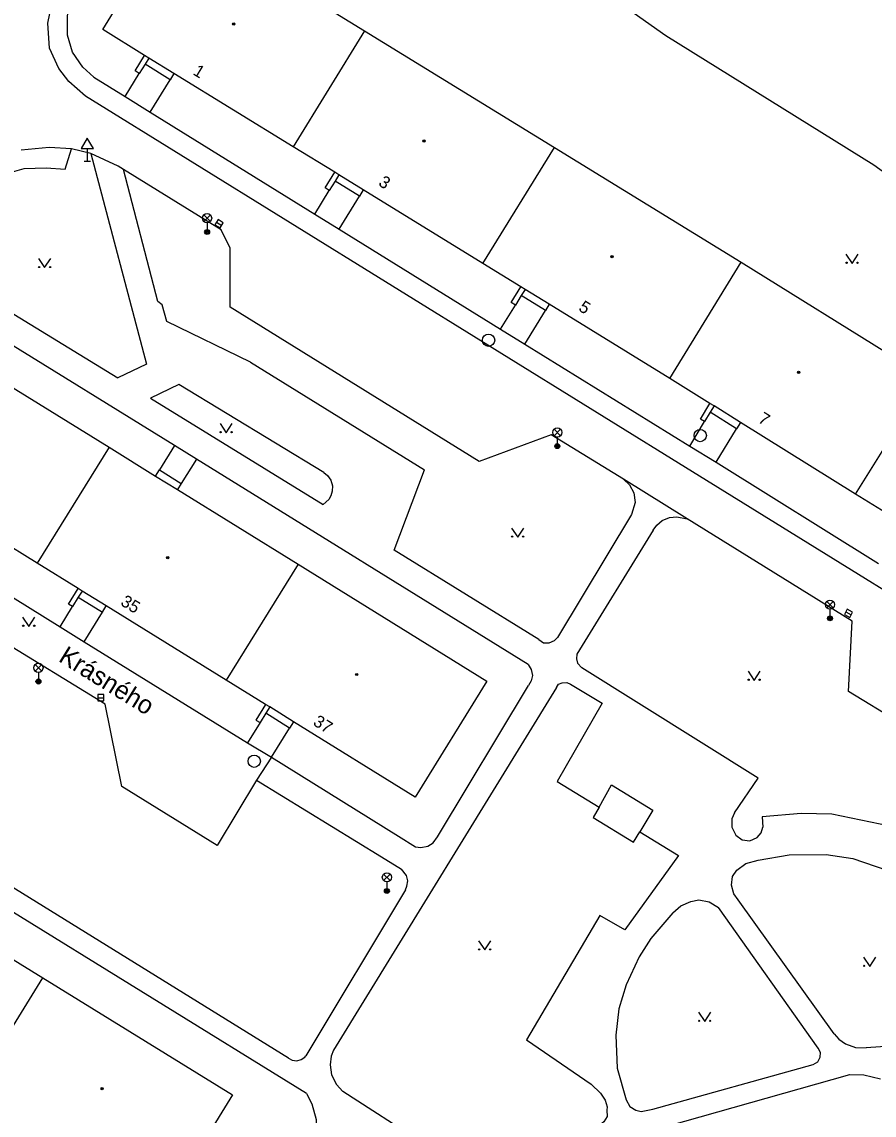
# Model space of a CAD drawing. Extents: x -598341 to -594502, y -1162301 to -1161406.
# Drawn here: x -594775.2 to -594705.4, y -1161589.1 to -1161499.6 of the extents above; entities that cross this region are included whole.
import ezdxf

# ---------------------------------------------------------------- set-up
doc = ezdxf.new("R2010")
doc.units = 0
for name, color, linetype in [('Vrstva 10', 7, 'Continuous'), ('Vrstva 11', 7, 'Continuous'), ('Vrstva 27', 7, 'Continuous'), ('Vrstva 33', 7, 'Continuous'), ('Vrstva 34', 7, 'Continuous'), ('Vrstva 36', 7, 'Continuous'), ('Vrstva 39', 7, 'Continuous'), ('Vrstva 46', 7, 'Continuous'), ('Vrstva 49', 7, 'Continuous'), ('Vrstva 5', 7, 'Continuous')]:
    doc.layers.add(name, color=color, linetype=linetype)

msp = doc.modelspace()

# ---------------------------------------------------------------- linework, layer by layer
at = {"layer": 'Vrstva 10'}
for p, q in [((-594772.93, -1161509.91), (-594775.22, -1161510.13)), ((-594771.1, -1161510.03), (-594772.93, -1161509.91)), ((-594769.52, -1161510.41), (-594771.1, -1161510.03)), ((-594767.27, -1161511.46), (-594769.52, -1161510.41)), ((-594766.83, -1161511.73), (-594767.27, -1161511.46)), ((-594758.85, -1161516.66), (-594766.83, -1161511.73)), ((-594758.11, -1161518.16), (-594758.85, -1161516.66)), ((-594758.12, -1161522.99), (-594758.11, -1161518.16)), ((-594737.73, -1161535.61), (-594758.12, -1161522.99)), ((-594731.85, -1161533.43), (-594737.73, -1161535.61)), ((-594725.93, -1161537.07), (-594731.85, -1161533.43)), ((-594720.72, -1161540.31), (-594725.93, -1161537.07)), ((-594785.33, -1161540.9), (-594772.03, -1161549.14)), ((-594707.22, -1161548.68), (-594720.72, -1161540.31)), ((-594768.35, -1161555.47), (-594789.84, -1161542.3)), ((-594707.53, -1161554.42), (-594707.22, -1161548.68)), ((-594772.03, -1161549.14), (-594770.06, -1161550.36)), ((-594770.06, -1161550.36), (-594756.69, -1161558.63)), ((-594697.74, -1161560.45), (-594707.53, -1161554.42)), ((-594766.98, -1161562.21), (-594768.35, -1161555.47)), ((-594756.69, -1161558.63), (-594754.73, -1161559.81)), ((-594754.73, -1161559.81), (-594755.95, -1161561.69)), ((-594759.18, -1161567.03), (-594766.98, -1161562.21)), ((-594755.95, -1161561.69), (-594759.18, -1161567.03))]:
    msp.add_line(p, q, dxfattribs=at)
for points in [[(-594771.32, -1161504.52), (-594772.13, -1161503.46), (-594772.9, -1161501.78), (-594773.04, -1161499.76), (-594772.69, -1161498.16), (-594772.22, -1161497.2)], [(-594615.8, -1161601.07), (-594662.39, -1161572.26), (-594719.72, -1161536.81), (-594769.96, -1161505.71), (-594771.32, -1161504.52)]]:
    msp.add_lwpolyline(points, dxfattribs=at)
at = {"layer": 'Vrstva 11'}
for p, q in [((-594765.08, -1161503.11), (-594765.55, -1161503.87)), ((-594764.76, -1161502.6), (-594765.08, -1161503.11)), ((-594763.02, -1161504.37), (-594765.08, -1161503.11)), ((-594769.26, -1161504.17), (-594766.7, -1161505.74)), ((-594766.7, -1161505.74), (-594765.55, -1161503.87)), ((-594762.71, -1161503.86), (-594763.02, -1161504.37)), ((-594764.65, -1161507.02), (-594763.02, -1161504.37)), ((-594766.7, -1161505.74), (-594764.65, -1161507.02)), ((-594764.65, -1161507.02), (-594751.18, -1161515.37)), ((-594771.62, -1161511.7), (-594771.1, -1161510.03)), ((-594749.21, -1161512.16), (-594749.52, -1161512.68)), ((-594749.52, -1161512.68), (-594750, -1161513.44)), ((-594747.54, -1161513.9), (-594749.52, -1161512.68)), ((-594751.18, -1161515.37), (-594750, -1161513.44)), ((-594749.2, -1161516.59), (-594747.54, -1161513.9)), ((-594747.23, -1161513.38), (-594747.54, -1161513.9)), ((-594751.18, -1161515.37), (-594749.2, -1161516.59)), ((-594749.2, -1161516.59), (-594735.99, -1161524.79)), ((-594781.79, -1161519.92), (-594767.3, -1161528.78)), ((-594762.67, -1161534.31), (-594783.13, -1161521.66)), ((-594734.3, -1161522.04), (-594734.77, -1161522.81)), ((-594733.98, -1161521.53), (-594734.3, -1161522.04)), ((-594732.32, -1161523.26), (-594734.3, -1161522.04)), ((-594735.99, -1161524.79), (-594734.77, -1161522.81)), ((-594732, -1161522.75), (-594732.32, -1161523.26)), ((-594734.01, -1161526.01), (-594732.32, -1161523.26)), ((-594735.99, -1161524.79), (-594734.01, -1161526.01)), ((-594734.01, -1161526.01), (-594720.51, -1161534.35)), ((-594756.45, -1161527.48), (-594742.22, -1161536.29)), ((-594750.46, -1161536.5), (-594762.3, -1161529.31)), ((-594718.52, -1161531.07), (-594718.84, -1161531.58)), ((-594718.84, -1161531.58), (-594719.3, -1161532.35)), ((-594716.68, -1161532.93), (-594718.84, -1161531.58)), ((-594720.51, -1161534.35), (-594719.3, -1161532.35)), ((-594716.36, -1161532.41), (-594716.68, -1161532.93)), ((-594718.34, -1161535.68), (-594716.68, -1161532.93)), ((-594762.67, -1161534.31), (-594763.9, -1161536.3)), ((-594760.88, -1161535.42), (-594762.67, -1161534.31)), ((-594720.51, -1161534.35), (-594718.34, -1161535.68)), ((-594760.88, -1161535.42), (-594762.11, -1161537.4)), ((-594733.72, -1161552.21), (-594760.88, -1161535.42)), ((-594764.21, -1161536.81), (-594763.9, -1161536.3)), ((-594763.9, -1161536.3), (-594762.11, -1161537.4)), ((-594718.34, -1161535.68), (-594705.07, -1161543.95)), ((-594762.11, -1161537.4), (-594762.42, -1161537.91)), ((-594725.28, -1161539.94), (-594731.34, -1161550.01)), ((-594723.5, -1161541.22), (-594729.74, -1161551.37)), ((-594770.22, -1161546.21), (-594770.54, -1161546.72)), ((-594770.54, -1161546.72), (-594771.01, -1161547.49)), ((-594770.54, -1161546.72), (-594768.56, -1161547.94)), ((-594772.03, -1161549.14), (-594771.01, -1161547.49)), ((-594770.06, -1161550.36), (-594768.56, -1161547.94)), ((-594768.56, -1161547.94), (-594768.25, -1161547.43)), ((-594731.42, -1161554.11), (-594749.67, -1161583.78)), ((-594741.15, -1161566.33), (-594733.71, -1161553.95)), ((-594754.88, -1161555.7), (-594755.2, -1161556.21)), ((-594755.67, -1161556.98), (-594756.69, -1161558.63)), ((-594755.2, -1161556.21), (-594755.67, -1161556.98)), ((-594753.25, -1161557.42), (-594755.2, -1161556.21)), ((-594752.93, -1161556.91), (-594753.25, -1161557.42)), ((-594754.73, -1161559.81), (-594753.25, -1161557.42)), ((-594755.95, -1161561.69), (-594745.72, -1161567.97)), ((-594712.38, -1161567.8), (-594709.36, -1161567.77)), ((-594745.72, -1161567.97), (-594744.1, -1161568.97)), ((-594751.86, -1161587.33), (-594781.69, -1161568.93)), ((-594743.76, -1161570.67), (-594751.92, -1161584.24)), ((-594710.01, -1161583.61), (-594718.16, -1161572.11)), ((-594708.69, -1161582.44), (-594716.56, -1161571.48)), ((-594721.9, -1161572.55), (-594723.7, -1161574.64)), ((-594722.37, -1161590.01), (-594707.41, -1161585.76))]:
    msp.add_line(p, q, dxfattribs=at)
for points in [[(-594744.77, -1161484.99), (-594722.47, -1161500.75), (-594705.44, -1161511.34), (-594693.39, -1161520.03), (-594678.98, -1161528.27), (-594666.01, -1161534.88), (-594661.61, -1161528.62)], [(-594769.26, -1161504.17), (-594770.18, -1161503.36), (-594771.01, -1161502.13), (-594771.43, -1161500.74), (-594771.43, -1161499.13), (-594771.1, -1161497.8)], [(-594765.55, -1161503.87), (-594765.89, -1161503.66), (-594765.11, -1161502.38)], [(-594769.52, -1161510.41), (-594764.96, -1161527.66), (-594767.3, -1161528.78)], [(-594780, -1161513.97), (-594778.7, -1161513.04), (-594776.88, -1161512.17), (-594774.96, -1161511.65), (-594773.18, -1161511.58), (-594771.62, -1161511.7)], [(-594756.45, -1161527.48), (-594763.3, -1161524.17), (-594763.67, -1161522.79), (-594764.02, -1161522.53), (-594766.83, -1161511.73)], [(-594750, -1161513.44), (-594750.34, -1161513.23), (-594749.55, -1161511.95)], [(-594734.77, -1161522.81), (-594735.11, -1161522.6), (-594734.32, -1161521.32)], [(-594762.3, -1161529.31), (-594764.64, -1161530.42), (-594750.5, -1161539.14)], [(-594719.3, -1161532.35), (-594719.64, -1161532.14), (-594718.86, -1161530.86)], [(-594732.86, -1161550.19), (-594744.7, -1161542.87), (-594742.22, -1161536.29)], [(-594750.46, -1161536.5), (-594750.14, -1161536.77), (-594749.89, -1161537.13), (-594749.75, -1161537.6), (-594749.76, -1161538.04), (-594749.88, -1161538.42), (-594750.03, -1161538.71), (-594750.5, -1161539.14)], [(-594725.93, -1161537.07), (-594725.44, -1161537.51), (-594725.08, -1161538.18), (-594724.99, -1161538.96), (-594725.28, -1161539.94)], [(-594723.5, -1161541.22), (-594723.21, -1161540.81), (-594722.77, -1161540.45), (-594722.18, -1161540.2), (-594721.57, -1161540.13), (-594720.72, -1161540.31)], [(-594771.01, -1161547.49), (-594771.35, -1161547.28), (-594770.56, -1161546)], [(-594732.86, -1161550.19), (-594732.47, -1161550.44), (-594732, -1161550.46), (-594731.58, -1161550.25), (-594731.34, -1161550.01)], [(-594729.74, -1161551.37), (-594729.78, -1161551.77), (-594729.69, -1161552.1), (-594729.33, -1161552.5)], [(-594733.72, -1161552.21), (-594733.48, -1161552.64), (-594733.39, -1161553.13), (-594733.48, -1161553.55), (-594733.71, -1161553.95)], [(-594716.84, -1161564.36), (-594714.9, -1161561.53), (-594729.33, -1161552.5)], [(-594753.34, -1161584.44), (-594799.98, -1161555.58), (-594802.68, -1161553.27)], [(-594731.42, -1161554.11), (-594731.25, -1161553.84), (-594730.95, -1161553.71), (-594730.56, -1161553.69), (-594730.28, -1161553.82)], [(-594730.28, -1161553.82), (-594727.67, -1161555.39), (-594731.36, -1161561.79), (-594727.92, -1161563.89)], [(-594755.22, -1161555.49), (-594756.01, -1161556.77), (-594755.67, -1161556.98)], [(-594754.73, -1161559.81), (-594744.34, -1161566.28), (-594742.96, -1161567.14)], [(-594727.92, -1161563.89), (-594726.91, -1161562.07), (-594723.52, -1161564.14), (-594724.6, -1161565.92)], [(-594727.92, -1161563.89), (-594728.4, -1161564.74), (-594725.11, -1161566.75), (-594724.6, -1161565.92)], [(-594716.84, -1161564.36), (-594717.06, -1161564.85), (-594717.08, -1161565.53), (-594716.75, -1161566.19), (-594716.23, -1161566.58), (-594715.6, -1161566.65), (-594714.99, -1161566.38), (-594714.66, -1161566), (-594714.53, -1161565.54)], [(-594704.2, -1161566.94), (-594704.14, -1161565.46), (-594708.88, -1161564.48), (-594711.39, -1161564.42), (-594714.58, -1161564.68), (-594714.53, -1161565.54)], [(-594724.6, -1161565.92), (-594721.44, -1161567.84), (-594725.83, -1161573.92), (-594727.86, -1161572.75), (-594733.86, -1161582.92), (-594728.58, -1161586.55), (-594727.81, -1161587.31)], [(-594742.96, -1161567.14), (-594742.5, -1161567.2), (-594741.93, -1161567.08), (-594741.51, -1161566.81), (-594741.15, -1161566.33)], [(-594716.56, -1161571.48), (-594716.9, -1161570.98), (-594717.1, -1161570.29), (-594717.01, -1161569.58), (-594716.66, -1161569.06), (-594715.93, -1161568.5), (-594714.91, -1161568.22), (-594712.38, -1161567.8)], [(-594709.36, -1161567.77), (-594707.17, -1161568.1), (-594704.38, -1161569.05), (-594702.46, -1161570.09), (-594700.74, -1161571.46)], [(-594743.76, -1161570.67), (-594743.66, -1161570.37), (-594743.59, -1161569.92), (-594743.69, -1161569.5), (-594744.1, -1161568.97)], [(-594721.9, -1161572.55), (-594721.25, -1161571.97), (-594720.43, -1161571.62), (-594719.77, -1161571.48), (-594718.91, -1161571.64), (-594718.16, -1161572.11)], [(-594723.7, -1161574.64), (-594724.66, -1161576.13), (-594725.71, -1161578.44), (-594726.3, -1161580.39), (-594726.55, -1161582.56), (-594726.44, -1161585.25), (-594725.71, -1161587.83), (-594725.4, -1161588.38), (-594724.92, -1161588.69), (-594724.48, -1161588.8)], [(-594708.69, -1161582.44), (-594708.3, -1161582.87), (-594707.77, -1161583.25), (-594706.95, -1161583.55), (-594706.08, -1161583.58)], [(-594699.75, -1161582.82), (-594703.35, -1161583.4), (-594706.08, -1161583.58)], [(-594749.67, -1161583.78), (-594749.85, -1161584.27), (-594749.92, -1161584.97), (-594749.82, -1161585.8), (-594749.42, -1161586.59), (-594748.89, -1161587.16)], [(-594710.42, -1161584.96), (-594710.04, -1161584.73), (-594709.83, -1161584.35), (-594709.82, -1161583.97), (-594710.01, -1161583.61)], [(-594753.34, -1161584.44), (-594753.03, -1161584.6), (-594752.66, -1161584.65), (-594752.3, -1161584.55), (-594752, -1161584.36), (-594751.92, -1161584.24)], [(-594724.48, -1161588.8), (-594723.52, -1161588.62), (-594710.42, -1161584.96)], [(-594707.41, -1161585.76), (-594706.26, -1161585.8), (-594704.9, -1161586.12)], [(-594751.86, -1161587.33), (-594751.44, -1161588.17), (-594751.09, -1161589.44), (-594751.07, -1161589.92), (-594751.01, -1161590.71), (-594751.18, -1161591.7), (-594751.76, -1161592.82)], [(-594740.61, -1161592.43), (-594742.38, -1161591.35), (-594748.89, -1161587.16)], [(-594727.81, -1161587.31), (-594727.43, -1161587.87), (-594727.28, -1161588.41), (-594727.29, -1161588.7), (-594727.28, -1161589.2), (-594727.54, -1161589.65), (-594727.95, -1161589.97)]]:
    msp.add_lwpolyline(points, dxfattribs=at)
at = {"layer": 'Vrstva 27'}
for p, q in [((-594759.232, -1161516.027), (-594758.808, -1161516.293)), ((-594707.741, -1161547.923), (-594707.299, -1161548.157)), ((-594768.94, -1161554.94), (-594768.44, -1161554.94))]:
    msp.add_line(p, q, dxfattribs=at)
for points in [[(-594759.365, -1161516.239), (-594758.941, -1161516.505), (-594758.675, -1161516.081), (-594759.099, -1161515.815)], [(-594707.858, -1161548.144), (-594707.416, -1161548.378), (-594707.182, -1161547.936), (-594707.624, -1161547.702)], [(-594768.94, -1161555.19), (-594768.44, -1161555.19), (-594768.44, -1161554.69), (-594768.94, -1161554.69)]]:
    msp.add_lwpolyline(points, close=True, dxfattribs=at)
for centre in [(-594736.97, -1161525.69), (-594719.65, -1161533.49), (-594756.14, -1161560.14)]:
    msp.add_circle(centre, 0.5, dxfattribs=at)
at = {"layer": 'Vrstva 33'}
for p, q in [((-594760.265, -1161515.97), (-594759.735, -1161515.44)), ((-594760.265, -1161515.44), (-594759.735, -1161515.97)), ((-594760, -1161516.08), (-594760, -1161516.83)), ((-594731.615, -1161533.5), (-594731.085, -1161532.97)), ((-594731.615, -1161532.97), (-594731.085, -1161533.5)), ((-594731.35, -1161533.61), (-594731.35, -1161534.36)), ((-594709.305, -1161547.59), (-594708.775, -1161547.06)), ((-594709.305, -1161547.06), (-594708.775, -1161547.59)), ((-594709.04, -1161547.7), (-594709.04, -1161548.45)), ((-594774.065, -1161552.76), (-594773.535, -1161552.23)), ((-594774.065, -1161552.23), (-594773.535, -1161552.76)), ((-594773.8, -1161552.87), (-594773.8, -1161553.62)), ((-594745.555, -1161569.9), (-594745.025, -1161569.37)), ((-594745.555, -1161569.37), (-594745.025, -1161569.9)), ((-594745.29, -1161570.01), (-594745.29, -1161570.76))]:
    msp.add_line(p, q, dxfattribs=at)
for centre, radius in [((-594760, -1161515.705), 0.375), ((-594760, -1161516.83), 0.2), ((-594760, -1161516.83), 0.145), ((-594760, -1161516.83), 0.0876), ((-594731.35, -1161533.235), 0.375), ((-594731.35, -1161534.36), 0.2), ((-594731.35, -1161534.36), 0.145), ((-594731.35, -1161534.36), 0.0876), ((-594709.04, -1161547.325), 0.375), ((-594709.04, -1161548.45), 0.2), ((-594709.04, -1161548.45), 0.145), ((-594709.04, -1161548.45), 0.0876), ((-594773.8, -1161552.495), 0.375), ((-594773.8, -1161553.62), 0.2), ((-594773.8, -1161553.62), 0.145), ((-594773.8, -1161553.62), 0.0876), ((-594745.29, -1161569.635), 0.375), ((-594745.29, -1161570.76), 0.2), ((-594745.29, -1161570.76), 0.145), ((-594745.29, -1161570.76), 0.0876)]:
    msp.add_circle(centre, radius, dxfattribs=at)
at = {"layer": 'Vrstva 34'}
for p, q in [((-594769.8, -1161510.012), (-594769.8, -1161511.03)), ((-594770.05, -1161511.03), (-594769.55, -1161511.03))]:
    msp.add_line(p, q, dxfattribs=at)
msp.add_lwpolyline([(-594770.3, -1161510.012), (-594769.3, -1161510.012), (-594769.8, -1161509.146)], close=True, dxfattribs=at)
at = {"layer": 'Vrstva 36'}
for points in [[(-594773.79, -1161519), (-594773.29, -1161519.75), (-594772.79, -1161519)], [(-594707.73, -1161518.65), (-594707.23, -1161519.4), (-594706.73, -1161518.65)], [(-594758.94, -1161532.51), (-594758.44, -1161533.26), (-594757.94, -1161532.51)], [(-594735.09, -1161541.06), (-594734.59, -1161541.81), (-594734.09, -1161541.06)], [(-594775.09, -1161548.35), (-594774.59, -1161549.1), (-594774.09, -1161548.35)], [(-594715.74, -1161552.77), (-594715.24, -1161553.52), (-594714.74, -1161552.77)], [(-594737.79, -1161574.83), (-594737.29, -1161575.58), (-594736.79, -1161574.83)], [(-594706.29, -1161576.18), (-594705.79, -1161576.93), (-594705.29, -1161576.18)], [(-594719.79, -1161580.68), (-594719.29, -1161581.43), (-594718.79, -1161580.68)]]:
    msp.add_lwpolyline(points, dxfattribs=at)
for centre in [(-594707.68, -1161519.35), (-594706.781, -1161519.35), (-594773.74, -1161519.7), (-594772.841, -1161519.7), (-594758.89, -1161533.21), (-594757.991, -1161533.21), (-594735.04, -1161541.76), (-594734.141, -1161541.76), (-594775.04, -1161549.05), (-594774.141, -1161549.05), (-594715.69, -1161553.47), (-594714.791, -1161553.47), (-594737.74, -1161575.53), (-594736.841, -1161575.53), (-594706.24, -1161576.88), (-594719.74, -1161581.38), (-594718.841, -1161581.38)]:
    msp.add_circle(centre, 0.05, dxfattribs=at)
at = {"layer": 'Vrstva 39'}
for centre, radius in [((-594757.82, -1161499.82), 0.09), ((-594757.82, -1161499.82), 0.0398), ((-594742.26, -1161509.39), 0.09), ((-594742.26, -1161509.39), 0.0398), ((-594726.87, -1161518.86), 0.09), ((-594726.87, -1161518.86), 0.0398), ((-594711.6, -1161528.31), 0.09), ((-594711.6, -1161528.31), 0.0398), ((-594763.22, -1161543.48), 0.09), ((-594763.22, -1161543.48), 0.0398), ((-594747.76, -1161553.04), 0.09), ((-594747.76, -1161553.04), 0.0398), ((-594768.59, -1161586.93), 0.09), ((-594768.59, -1161586.93), 0.0398)]:
    msp.add_circle(centre, radius, dxfattribs=at)
at = {"layer": 'Vrstva 5'}
for p, q in [((-594768.54, -1161500.27), (-594762.71, -1161490.78)), ((-594762.71, -1161490.78), (-594747.11, -1161500.37)), ((-594765.11, -1161502.38), (-594768.54, -1161500.27)), ((-594747.11, -1161500.37), (-594752.95, -1161509.86)), ((-594747.11, -1161500.37), (-594731.59, -1161509.91)), ((-594764.76, -1161502.6), (-594765.11, -1161502.38)), ((-594762.71, -1161503.86), (-594764.76, -1161502.6)), ((-594752.95, -1161509.86), (-594762.71, -1161503.86)), ((-594749.55, -1161511.95), (-594752.95, -1161509.86)), ((-594737.43, -1161519.41), (-594731.59, -1161509.91)), ((-594731.59, -1161509.91), (-594716.31, -1161519.3)), ((-594749.21, -1161512.16), (-594749.55, -1161511.95)), ((-594747.23, -1161513.38), (-594749.21, -1161512.16)), ((-594737.43, -1161519.41), (-594747.23, -1161513.38)), ((-594734.32, -1161521.32), (-594737.43, -1161519.41)), ((-594722.15, -1161528.81), (-594716.31, -1161519.3)), ((-594716.31, -1161519.3), (-594701.04, -1161528.8)), ((-594733.98, -1161521.53), (-594734.32, -1161521.32)), ((-594732, -1161522.75), (-594733.98, -1161521.53)), ((-594722.15, -1161528.81), (-594732, -1161522.75)), ((-594783.49, -1161524.88), (-594768.02, -1161534.45)), ((-594718.86, -1161530.86), (-594722.15, -1161528.81)), ((-594706.94, -1161538.28), (-594701.04, -1161528.8)), ((-594718.52, -1161531.07), (-594718.86, -1161530.86)), ((-594716.36, -1161532.41), (-594718.52, -1161531.07)), ((-594706.94, -1161538.28), (-594716.36, -1161532.41)), ((-594768.02, -1161534.45), (-594773.89, -1161543.94)), ((-594768.02, -1161534.45), (-594764.21, -1161536.81)), ((-594764.21, -1161536.81), (-594762.42, -1161537.91)), ((-594773.89, -1161543.94), (-594783.52, -1161537.98)), ((-594762.42, -1161537.91), (-594752.56, -1161544.02)), ((-594703.39, -1161540.49), (-594706.94, -1161538.28)), ((-594770.56, -1161546), (-594773.89, -1161543.94)), ((-594752.56, -1161544.02), (-594758.43, -1161553.51)), ((-594752.56, -1161544.02), (-594737.1, -1161553.58)), ((-594770.22, -1161546.21), (-594770.56, -1161546)), ((-594768.25, -1161547.43), (-594770.22, -1161546.21)), ((-594758.43, -1161553.51), (-594768.25, -1161547.43)), ((-594755.22, -1161555.49), (-594758.43, -1161553.51)), ((-594737.1, -1161553.58), (-594742.97, -1161563.07)), ((-594754.88, -1161555.7), (-594755.22, -1161555.49)), ((-594752.93, -1161556.91), (-594754.88, -1161555.7)), ((-594742.97, -1161563.07), (-594752.93, -1161556.91)), ((-594788.74, -1161568.43), (-594773.44, -1161577.86)), ((-594779.31, -1161587.38), (-594773.44, -1161577.86)), ((-594773.44, -1161577.86), (-594757.91, -1161587.43)), ((-594757.91, -1161587.43), (-594763.81, -1161596.97))]:
    msp.add_line(p, q, dxfattribs=at)

# ---------------------------------------------------------------- texts
at = {"layer": 'Vrstva 46'}
for s, height, rotation, p in [('1', 1, 328.78, (-594761.22, -1161503.91)), ('3', 1, 326.29, (-594746.05, -1161512.97)), ('5', 1, 327.13, (-594729.68, -1161523.21)), ('7', 1, 327.9, (-594714.99, -1161532.35)), ('35', 1, 328.77, (-594767.15, -1161547.32)), ('37', 0.9999, 327.75, (-594751.4, -1161557.13))]:
    msp.add_text(s, height=height, rotation=rotation, dxfattribs=at).set_placement(p)
at = {"layer": 'Vrstva 49'}
msp.add_text('Krásného', height=1.5, rotation=328.26, dxfattribs=at).set_placement((-594772.24, -1161551.91))

doc.saveas('drawing.dxf')
